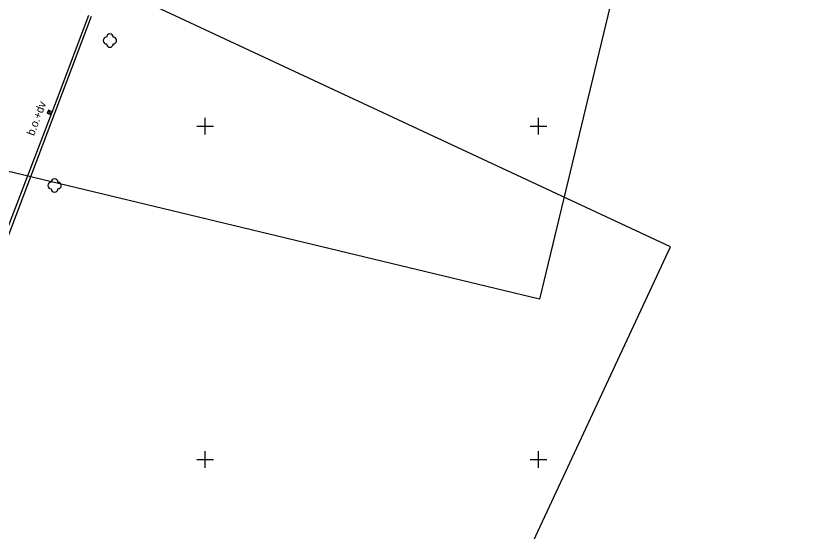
# Model space of a CAD drawing. Extents: x -599151 to -598424, y -1163476 to -1161924.
# Drawn here: x -598689.2 to -598628.7, y -1162730.4 to -1162691.7 of the extents above; entities that cross this region are included whole.
import ezdxf

# ---------------------------------------------------------------- set-up
doc = ezdxf.new("R2010")
doc.units = 0
for name, color, linetype in [('Vrstva 1', 7, 'Continuous'), ('Vrstva 14', 7, 'Continuous'), ('Vrstva 25', 7, 'Continuous'), ('Vrstva 49', 7, 'Continuous'), ('Vrstva 62', 7, 'Continuous'), ('Vrstva 63', 7, 'Continuous'), ('Vrstva 7', 7, 'Continuous')]:
    doc.layers.add(name, color=color, linetype=linetype)

msp = doc.modelspace()

# ---------------------------------------------------------------- linework, layer by layer
at = {"layer": 'Vrstva 1'}
for p, q in [((-598563.987, -1162355.651), (-598649.916, -1162712.964)), ((-598640.084, -1162709.057), (-598707.36, -1162677.641)), ((-598649.916, -1162712.964), (-598722.107, -1162695.603)), ((-598662.298, -1162756.627), (-598640.084, -1162709.057))]:
    msp.add_line(p, q, dxfattribs=at)
at = {"layer": 'Vrstva 14'}
for centre in [(-598682.13, -1162693.58), (-598686.28, -1162704.44)]:
    msp.add_circle(centre, 0.00025, dxfattribs=at)
for centre, start, end in [((-598682.13, -1162693.33), 0, 179.99999), ((-598682.38, -1162693.58), 89.99999, 269.99999), ((-598681.88, -1162693.58), 270, 89.99999), ((-598682.13, -1162693.83), 179.99999, 359.99999), ((-598686.28, -1162704.19), 0, 179.99999), ((-598686.53, -1162704.44), 89.99999, 269.99999), ((-598686.03, -1162704.44), 270, 89.99999), ((-598686.28, -1162704.69), 179.99999, 359.99999)]:
    msp.add_arc(centre, 0.25, start, end, dxfattribs=at)
at = {"layer": 'Vrstva 25'}
msp.add_line((-598686.715, -1162699.077), (-598686.625, -1162698.843), dxfattribs=at)
msp.add_lwpolyline([(-598686.598, -1162699.121), (-598686.509, -1162698.888), (-598686.742, -1162698.799), (-598686.831, -1162699.032)], close=True, dxfattribs=at)
at = {"layer": 'Vrstva 62'}
for p, q in [((-598675, -1162700.625), (-598675, -1162699.375)), ((-598650, -1162700.625), (-598650, -1162699.375)), ((-598675.625, -1162700), (-598674.375, -1162700)), ((-598650.625, -1162700), (-598649.375, -1162700)), ((-598675, -1162725.625), (-598675, -1162724.375)), ((-598650, -1162725.625), (-598650, -1162724.375)), ((-598675.625, -1162725), (-598674.375, -1162725)), ((-598650.625, -1162725), (-598649.375, -1162725))]:
    msp.add_line(p, q, dxfattribs=at)
at = {"layer": 'Vrstva 63'}
msp.add_lwpolyline([(-598697.52, -1162728.69), (-598683.522, -1162691.742)], dxfattribs=at)
at = {"layer": 'Vrstva 7'}
for points in [[(-598697.52, -1162728.69), (-598683.522, -1162691.742)], [(-598690.36, -1162709.11), (-598686.141, -1162698.089), (-598683.709, -1162691.671)]]:
    msp.add_lwpolyline(points, dxfattribs=at)

# ---------------------------------------------------------------- texts
at = {"layer": 'Vrstva 49'}
msp.add_text('b.o.+dv', height=0.6, rotation=69.39905, dxfattribs=at).set_placement((-598687.826, -1162700.76))

doc.saveas('drawing.dxf')
